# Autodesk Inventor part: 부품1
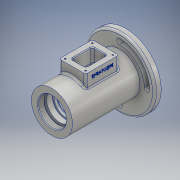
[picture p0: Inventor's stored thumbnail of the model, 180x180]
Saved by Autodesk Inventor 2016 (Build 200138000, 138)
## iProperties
Created: 2017-05
Part Number: 부품1
Material: 알루미늄 6061
Document SubType Name: Modeling
Designer: USER
Density: 2.7 g/cm^3
Appearance: 알루미늄 - 평지
Mass: 676.85 g
Surface Area: 618.164 cm^2
Volume: 250.685 cm^3
Author: USER
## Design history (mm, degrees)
sketch "스케치2"
  geometry: C1 r 53 at (0, 0); 1 further point
  constraints: 1 centre point, 1 coincident
  dimensions: "d0" = 106 diameter of C1
extrude "돌출1" new body sketch "스케치2" distance "d1" = 10; taper "d2" = 0 deg
sketch "스케치3"
  geometry: A1 r 41.5 centre (0, 0) between (0, 41.5) and (-41.5, 0); A2 r 4 centre (0, 41.5) between (0, 37.5) and (0, 45.5); A3 r 4 centre (-41.5, 0) between (-45.5, 0) and (-37.5, 0); A4 r 4 centre (41.5, 0) between (45.5, 0) and (37.5, 0); A5 r 4 centre (0, -41.5) between (0, -37.5) and (0, -45.5); A6 r 37.5 centre (0, 0) between (0, 37.5) and (-37.5, 0); A7 r 37.5 centre (0, 0) between (0, -37.5) and (37.5, 0); A8 r 45.5 centre (0, 0) between (0, 45.5) and (-45.5, 0); A9 r 45.5 centre (0, 0) between (0, -45.5) and (45.5, 0); 1 further point
  constraints: 20 point on circle, 9 centre point, 4 tangent, 3 coincident, 2 horizontal alignment, 2 vertical alignment
  dimensions: "d4" = 83 diameter of A1; "d5" = 8 diameter of A2; "d6" = 8 diameter of A3; "d7" = 8 diameter of A4; "d8" = 8 diameter of A5
extrude "돌출2" cut sketch "스케치3" distance "d9" = 10; taper "d10" = 0 deg
sketch "스케치4"
  geometry: C1 r 31 at (0, 0); 1 further point
  constraints: 1 centre point, 1 coincident
  dimensions: "d11" = 62 diameter of C1
extrude "돌출3" join sketch "스케치4" distance "d12" = 3; taper "d13" = 0 deg
sketch "스케치5"
  geometry: C1 r 31 at (0, 0); 1 further point
  constraints: 1 centre point, 1 coincident
  dimensions: "d14" = 62 diameter of C1
extrude "돌출4" join sketch "스케치5" distance "d15" = 102; taper "d16" = 0 deg
node "작업 평면1"
sketch "스케치6"
  geometry: L1 (37.5, 10)-(37.5, 0) reference; L2 (37.5, 0)-(31, 0) reference; L3 (31, 0)-(31, -102) reference; L4 (31, -102)-(-31, -102) reference; L5 (-31, -102)-(-31, 0) reference; L6 (-31, 0)-(-37.5, 0) reference; L7 (-37.5, 0)-(-37.5, 10) reference; L8 (-37.5, 10)-(-31, 10) reference; L9 (-31, 10)-(-31, 13) reference; L10 (-31, 13)-(31, 13) reference; L11 (31, 13)-(31, 10) reference; L12 (31, 10)-(37.5, 10) reference; L13 (-53, 0)-(-53, 10) reference; L14 (-53, 10)-(-45.5, 10) reference; L15 (-45.5, 10)-(-45.5, 0) reference; L16 (-45.5, 0)-(-53, 0) reference; L17 (53, 10)-(53, 0) reference; L18 (53, 0)-(45.5, 0) reference; L19 (45.5, 0)-(45.5, 10) reference; L20 (45.5, 10)-(53, 10) reference; L21 (0, -102)-(0, 13); L22 (31, 13)-(-31, 13) reference; L23 (21, -102)-(21, -93); L24 (21, -93)-(24, -93); L25 (24, -93)-(24, -90); L26 (24, -90)-(20, -90); L27 (20, -90)-(20, -81); L28 (20, -81)-(17.5, -81); L29 (17.5, -81)-(17.5, -77.75); L30 (17.5, -77.75)-(18.5, -77.75); L31 (18.5, -77.75)-(18.5, -76); L32 (18.5, -76)-(17.5, -76); L33 (17.5, -76)-(17.5, -65); L34 (17.5, -65)-(26, -65); L35 (26, -65)-(26, -27); L36 (26, -27)-(17.5, -27); L37 (17.5, -27)-(17.5, -16); L38 (17.5, -16)-(16.5, -16); L39 (16.5, -16)-(16.5, -11); L40 (16.5, -11)-(10, -11); L41 (10, -11)-(10, -8.3); L42 (10, -8.3)-(12.5, -8.3); L43 (12.5, -8.3)-(12.5, -1); L44 (12.5, -1)-(16, -1); L45 (16, -1)-(22, 13); 1 further point
  constraints: 48 end point, 17 perpendicular, 4 point on line, 2 horizontal, 2 midpoint, 2 vertical
  dimensions: "d18" = 42 diameter of L23 L21; "d19" = 9 distance of L23.start L23.end; "d20" = 48 diameter of L25 L21; "d21" = 40 diameter of L27 L21; "d22" = 3 distance of L24.end L25.end; "d23" = 35 diameter of L29 L21; "d24" = 21 distance between parallel lines of L28 L4; "d25" = 37 diameter of L31 L21; "d26" = 1.75 distance of L30.end L31.end; "d27" = 26 distance between parallel lines of L4 L32; "d28" = 11 distance of L32.end L33.end; "d29" = 35 diameter of L33 L21; "d30" = 52 diameter of L35 L21; "d31" = 38 distance of L34.end L35.end; "d32" = 11 distance of L36.end L37.end; "d33" = 25 diameter of L43 L21; "d34" = 7.3 distance of L42.end L43.end; "d35" = 2.7 distance of L40.end L41.end; "d36" = 20 diameter of L41 L21; "d37" = 5 distance of L38.end L39.end; "d39" = 33 diameter of L39 L21; "d40" = 32 diameter of L44.end L21; "d41" = 44 diameter of L45.end L21
revolve "회전1" sketch "스케치6" stored, may be unused: angle "d42" = 90 deg
feature "스레드1" dims "d43" = 10, "d44" = 0
chamfer "모따기1" distance "d45" = 1; stored, may be unused: second distance "d46" = 2, angle "d47" = 45 deg
chamfer "모따기2" distance "d48" = 1; stored, may be unused: second distance "d49" = 2, angle "d50" = 45 deg
chamfer "모따기3" distance "d51" = 0.7; stored, may be unused: second distance "d52" = 2, angle "d53" = 30 deg
fillet "모깎기1" dims "d54" = 3
fillet "모깎기2" dims "d55" = 3
fillet "모깎기3" dims "d56" = 3
fillet "모깎기4" dims "d57" = 0.3
node "작업 평면2"
sketch "스케치7"
  geometry: L1 (-31, 0)-(-31, -102) reference; L2 (-31, -102)-(31, -102) reference; L3 (31, 0)-(31, -102) reference; L4 (-20, -71)-(20, -71); L5 (20, -71)-(20, -21); L6 (20, -21)-(-20, -21); L7 (-20, -21)-(-20, -71); 3 further points
  constraints: 8 end point, 2 midpoint, 2 parallel, 1 horizontal, 1 perpendicular, 1 vertical alignment
  dimensions: "d59" = 31 distance between parallel lines of L4 L2; "d60" = 40 distance of L4.start L4.end; "d61" = 50 distance of L4.end L5.end
extrude "돌출5" join sketch "스케치7" stored distance "d62" = 102; taper "d63" = 0 deg
sketch "스케치8"
  geometry: L1 (11, 62)-(-11, 62); L2 (-11, 62)-(-11, 30); L3 (-11, 30)-(11, 30); L4 (11, 30)-(11, 62); L5 (20, 71)-(-20, 71) reference; L6 (11, 46)-(-11, 46); L7 (31, 102)-(-31, 102) reference; 3 further points
  constraints: 10 end point, 4 midpoint, 2 parallel, 1 horizontal, 1 perpendicular, 1 vertical alignment
  dimensions: "d64" = 22 distance of L1.start L1.end; "d65" = 32 distance of L1.end L2.end; "d66" = 56 distance between parallel lines of L7 L6
extrude "돌출6" cut sketch "스케치8" stored distance "d67" = 102; taper "d68" = 0 deg
fillet "모깎기5" dims "d69" = 3
fillet "모깎기6" dims "d70" = 3
fillet "모깎기7" dims "d71" = 3
chamfer "모따기4" distance "d72" = 1; stored, may be unused: second distance "d73" = 2, angle "d74" = 30 deg
sketch "스케치9"
  geometry: L1 (15.5, 66.5)-(-15.5, 66.5); L2 (-15.5, 66.5)-(-15.5, 25.5); L3 (-15.5, 25.5)-(15.5, 25.5); L4 (15.5, 25.5)-(15.5, 66.5); L5 (17, 71)-(-17, 71) reference; L6 (15.5, 46)-(-15.5, 46); L7 (31, 102)-(-31, 102) reference; 3 further points
  constraints: 10 end point, 4 midpoint, 2 parallel, 1 horizontal, 1 perpendicular, 1 vertical alignment
  dimensions: "d75" = 31 distance of L1.start L1.end; "d76" = 41 distance of L3.end L1.start; "d77" = 56 distance between parallel lines of L7 L6
hole "구멍1" sketch "스케치9" at (15.5, 66.5), (15.5, 25.5), (-15.5, 25.5), (-15.5, 66.5) diameter "d78" = 2.459; stored, may be unused: countersink angle "d82" = 90 deg, drill point angle "d84" = 118 deg; dims "d79" = 6, "d80" = 4, "d81" = 2, "d83" = 8
fillet "모깎기8" dims "d85" = 3
node "작업 평면3"
sketch "스케치10"
  geometry: L1 (0, 0)-(44, 0) reference; L2 (-34, -13)-(-34, -75) reference; 2 further points
  constraints: 1 other
  dimensions: "d87" = 8 distance from line of L1 point (22, -8); "d88" = 56 distance from line of L2 point (22, -8)
feature "엠보싱1" sketch "스케치10" dims "d89" = 0.5, "d90" = 0
chamfer "모따기5" distance "d91" = 1; stored, may be unused: second distance "d92" = 2, angle "d93" = 30 deg
fillet "모깎기9" dims "d94" = 0.3
node "솔리드1"
node "절단 모서리 투영1"
other parameters: "d17" = 0, "d58" = 44, "d86" = 0.5
